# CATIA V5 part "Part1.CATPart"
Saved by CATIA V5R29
Part number: c03
Bounding box of the stored display mesh (mm): x -38 to 35, y -200 to 200, z 50.137 to 235.137
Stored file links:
  C:\Users\제5강의실-23\Desktop\Part1.CATPart
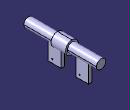
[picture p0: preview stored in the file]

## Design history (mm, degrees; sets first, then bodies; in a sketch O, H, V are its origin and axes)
Body1 (main body)
  DatumCurve1
  DatumSurface1
  Sketch1 on zx-plane, origin (0, 0, 0), H (-1, 0, 0), V (0, 0, 1)
    circle A1 centre (0, 200.1365) radius 25
    reference projected circle E1 centre (0, 200.1365) radius 30 from edge of DatumCurve1
    radius A1 = 25
    concentricity: A1 E1
  Pad1: profile Sketch1, direction (0, 1, 0), length 200, mirrored extent
  Sketch2 on end face of Pad1, origin (0, 200, 0), H (-1, 0, 0), V (0, 0, 1)
    line L1 (20, 200.1365) -> (25, 200.1365)
    line L2 (20, 50.1365) -> (20, 200.1365)
    line L3 (25, 200.1365) -> (25, 150.1365)
    line L4 (25, 150.1365) -> (38, 150.1365)
    line L5 (38, 150.1365) -> (38, 50.1365)
    line L6 (38, 50.1365) -> (20, 50.1365)
    point P7 (0, 200.1365)
    reference projected circle E2 centre (0, 200.1365) radius 25 from edge [face of Pad1 from Sketch1.A1 | end face of Pad1]
    length L1 = 5
    distance L3 P7 = 25
    distance L6 L1 = 150
    distance L4 L1 = 50
    distance L5 L2 = 18
    horizontal: L1 H, L4 H, L6 H
    vertical: L2 V, L3 V, L5 V
    concentricity: P7 E2
    coincidence: L1 P7
  DatumSurface2
  Plane1: type Offset, RefPlane DatumSurface2, Offset 0
  Sketch3 on Plane1, origin (0, 111, 0), H (-1, 0, 0), V (0, 0, 1)
  Pad2: profile Sketch3, direction (0, -1, 0), length 222
  Fillet1: radius 10, on edge [face of Pad2 | face of Pad2] (x2); edge [face of Pad1 from Sketch1.A1 | face of Pad2]
  DatumSurface3
  DatumSurface4
  Sketch4 on face of Pad2, origin (0, 0, 50.1365), H (1, 0, 0), V (0, -1, 0)
    projected circle E1 centre (-29.05, -95) radius 4.15 from face of DatumSurface3
    projected circle E2 centre (-29.05, 55) radius 4.15 from face of DatumSurface4
  Pocket1: profile Sketch4, direction (0, 0, 1), length 70
  Chamfer1: length 1, angle 45, on edge [face of Pad2 | face of Pocket1 from Sketch4.E2]; edge [face of Pad2 | face of Pocket1 from Sketch4.E1]
  DatumCurve2
  Sketch5 on zx-plane, origin (0, 0, 0), H (-1, 0, 0), V (0, 0, 1)
    circle A1 centre (0, 200.1365) radius 25
    reference projected circle E1 centre (0, 200.1365) radius 25 from edge of DatumCurve2
    coincidence: A1 E1
  Pocket2: profile Sketch5, direction (0, 1, 0), length 40, mirrored extent, outer side
  Sketch6 on end face of Pocket2, origin (0, 40, 0), H (0, 0, 1), V (-1, 0, 0)
    circle A1 centre (200.1365, 0) radius 35
    point P1 (200.1365, 0)
    reference projected point E1 (200.1365, 0) from axis of face of Pocket2
    radius A1 = 35
    coincidence: P1 H
    concentricity: A1 E1
  Pad3: profile Sketch6, direction (0, -1, 0), up to start face of Pocket2
  DatumCurve3
  DatumCurve4
  Sketch7 on face of Pad2, origin (-38, 0, 0), H (0, -1, 0), V (0, 0, 1)
    projected circle E1 centre (88.5, 70.1365) radius 3.5 from edge of DatumCurve3
    projected circle E2 centre (-62.5, 70.1365) radius 3.5 from edge of DatumCurve4
  Pocket3: profile Sketch7, direction (1, 0, 0), through (limit type 3)
  DatumSurface5
  Sketch8 on end face of Pad2, origin (0, -111, 0), H (1, 0, 0), V (0, 0, 1)
    line L1 (-38, 50.1365) -> (-25, 50.1365)
    line L2 (-25, 50.1365) -> (-25, 90.1365)
    line L3 (-25, 90.1365) -> (-38, 90.1365)
    line L4 (-38, 90.1365) -> (-38, 50.1365)
    reference intersected line E1 (-20, 50.1365) -> (-38, 50.1365) from face of Pad2
    reference intersected line E2 (-38, 50.1365) -> (-38, 150.1365) from face of Pad2
    reference intersected line E3 through (0, 90.1365) direction (-1, 0) from face of DatumSurface5
    reference intersected line E4 (-20, 200.1365) -> (-20, 50.1365) from face of Pad2
    distance L1 E1 = 0
    distance L4 E2 = 0
    distance L3 E3 = 0
    distance L2 E4 = 5
    horizontal: L1 H, L3 H
    vertical: L2 V, L4 V
  Pocket4: profile Sketch8, direction (0, 1, 0), length 45
  Sketch9 on end face of Pocket2, origin (0, 40, 0), H (1, 0, 0), V (0, 0, 1)
  Pocket5: profile Sketch9, direction (0, 1, 0), length 45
